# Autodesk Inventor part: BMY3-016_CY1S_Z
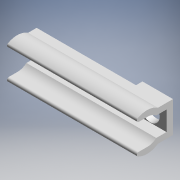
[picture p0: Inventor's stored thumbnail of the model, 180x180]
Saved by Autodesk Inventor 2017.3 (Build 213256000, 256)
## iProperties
Part Number: BMY3-016_CY1S_Z
Material: Generic
Catalog Web Link: www.cadenas.de
Description: CY1S-Z_SM-Magnetically Coupled Rodless Cylinder Slider Type/Slide Bearing
Vendor: SMC
Document SubType Name: Modeling
Designer: partserver
Manufacturer: SMC
Mass: 0.175472 g
Surface Area: 4.85378 cm^2
Volume: 0.175472 cm^3
Density: 1 g/cm^3
Appearance: PSOLRGB-255-255-255
Category: PARTsolutions
Company: SMC
Title: BMY3-016_CY1S_Z
Author: Cadenas PARTsolutions
Comments: Magnetically Coupled Rodless Cylinder Slider Type/Slide Bearing
PSOL_IDENT_0: {$CADENAS_DATA\23d-libs\smc_jp\actuator\rodless_cylinders\cy1\cy1s_z\parts\cy1s_z_sm.prj},173 {VTYP=
PSOL_IDENT_1: 3D},{NB=BMY3-016_CY1S_Z},{LINA=BMY3-016_CY1S_Z},{NN=CY1S-Z_SM},{DATE=09.12.2020 02:54:14},{GEOMDATE=
PSOL_IDENT_2: 09.03.2020 08:58:35},{VERSION=},{LINEID=10},{WBVAR=},{WBNUMERIC=}  {NB=BMY3-016_CY1S_Z},{LINA=BMY3-0
PSOL_IDENT_3: 16_CY1S_Z},{KT=DUMMY},{MODEL=BMY3-016},{THREAD2=MIN},{POS=MIN},{STOP=MIN}
NB: BMY3-016_CY1S_Z
NN: CY1S-Z_SM
NT: Magnetically Coupled Rodless Cylinder Slider Type/Slide Bearing
NBSYN: $MODEL._CY1S_Z
LINA: BMY3-016_CY1S_Z
CATALOG: SMC (JP
MODEL: BMY3-016
THREAD2: 0
POS: 0
STOP: 0
SUPPLIER: SMC
ARTICLENO: BMY3-016_CY1S_Z
BOMINFO: BMY3-016_CY1S_Z
CREATOR: CADENAS GmbH
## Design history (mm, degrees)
sketch "Sketch_1"
  geometry: L1 (-2, -1.365)-(-2, 0); L2 (-1.5, 1.323)-(-1.5, 2.9); L3 (-1.5, 2.9)-(1.5, 2.9); L4 (1.5, 2.9)-(1.5, 1.323); L5 (2, 0)-(2, -1.365); L6 (2.4, 1.572)-(2.4, 3.9); L7 (2.4, 3.9)-(-2.4, 3.9); L8 (-2.4, 3.9)-(-2.4, 1.572); A1 r 2.925 centre (0, -0.1) between (-2.4, 1.572) and (-2.563, -1.51); A2 r 0.3 centre (-2.3, -1.365) between (-2.563, -1.51) and (-2, -1.365); A3 r 2 centre (0, 0) between (-1.5, 1.323) and (-2, 0); A4 r 2 centre (0, 0) between (2, 0) and (1.5, 1.323); A5 r 0.3 centre (2.3, -1.365) between (2, -1.365) and (2.563, -1.51); A6 r 2.925 centre (0, -0.1) between (2.563, -1.51) and (2.4, 1.572)
  constraints: 16 end point, 12 point on circle, 6 centre point
extrude "Extrusion1" join sketch "Sketch_1" distance "d0" = 20; taper "d1" = 0 deg
sketch "Sketch_2"
  geometry: L1 (-2.4, 2.9)-(2.4, 2.9); L2 (2.4, 2.9)-(2.4, 3.9); L3 (2.4, 3.9)-(-2.4, 3.9); L4 (-2.4, 3.9)-(-2.4, 2.9)
  constraints: 8 end point
extrude "Extrusion2" cut sketch "Sketch_2" distance "d2" = 18; taper "d3" = 0 deg
sketch "Sketch_3"
  geometry: L1 (2, 0)-(2, 3.9); L2 (2, 3.9)-(3.45, 3.9); L3 (3.45, 3.9)-(3.45, 0); L4 (3.45, 0)-(2, 0); L5 (2, 0)-(2, 3.9)
  constraints: 10 end point
revolve "Revolution1" sketch "Sketch_3" stored, may be unused: angle "d4" = 360 deg
node "SM_BODY_XY"
node "SM_BODY_YZ"
node "SM_BODY_ZX"
node "SM_BODY_X"
node "SM_BODY_Y"
node "SM_BODY_Z"
node "SM_BODY_Center"
node "SM_SW_XY"
node "SM_SW_YZ"
node "SM_SW_ZX"
node "SM_SW_X"
node "SM_SW_Y"
node "SM_SW_Z"
node "SM_SW_Center"
body "Solid1"
